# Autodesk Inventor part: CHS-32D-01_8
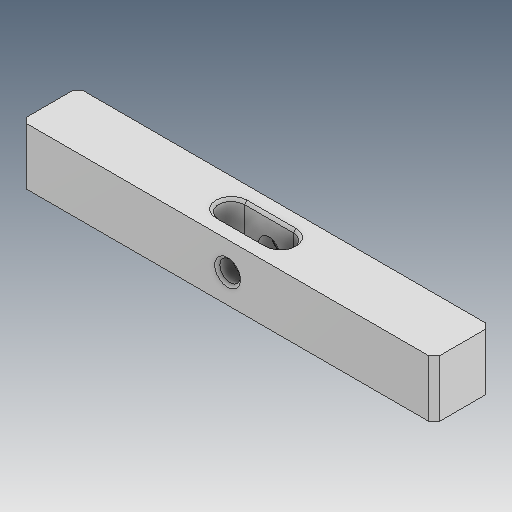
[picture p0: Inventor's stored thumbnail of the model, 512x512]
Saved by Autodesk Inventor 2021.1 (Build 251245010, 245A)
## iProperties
Created: 2021-05
Part Number: CHS-32D-01_8
Material: Ogólny
Document SubType Name: Modeling
Designer: user
Density: 1 g/cm^3
Appearance: Domyślna
Author: user
Revision Number: ÈÎºÎ
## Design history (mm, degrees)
feature "ÊäÈë1"
node "Bryła1"
